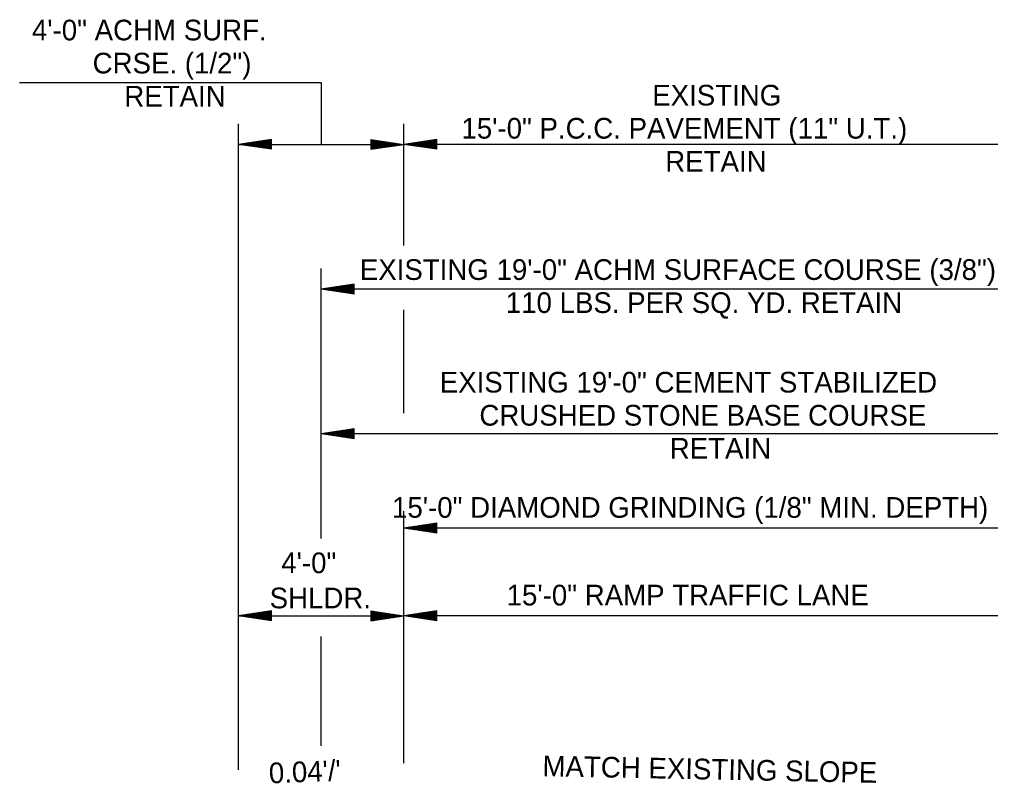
# Model space of a CAD drawing. Extents: x 60325 to 61047, y 53669 to 53767.
# Drawn here: x 60750.78 to 60774.27, y 53740.22 to 53758.7 of the extents above; entities that cross this region are included whole.
import ezdxf

# ---------------------------------------------------------------- set-up
doc = ezdxf.new("R2010")
doc.units = 0
doc.layers.add('R_Border', color=7, linetype='Continuous')
doc.layers.add('R_Border Prem', color=7, linetype='Continuous')

msp = doc.modelspace()

# ---------------------------------------------------------------- linework, layer by layer
at = {"layer": 'R_Border'}
for p, q in [((60760.077, 53740.712), (60760.077, 53746.806)), ((60760.877, 53746.514), (60760.077, 53746.394)), ((60760.877, 53746.494), (60760.21, 53746.394)), ((60760.877, 53746.474), (60760.348, 53746.394)), ((60760.877, 53746.454), (60760.481, 53746.394)), ((60760.877, 53746.434), (60760.617, 53746.394)), ((60760.877, 53746.274), (60760.877, 53746.514)), ((60775.077, 53746.394), (60760.077, 53746.394)), ((60760.877, 53746.274), (60760.077, 53746.394)), ((60760.877, 53746.294), (60760.21, 53746.394)), ((60760.877, 53746.315), (60760.348, 53746.394)), ((60760.877, 53746.335), (60760.481, 53746.394)), ((60760.877, 53746.356), (60760.617, 53746.394)), ((60760.877, 53746.413), (60760.75, 53746.394)), ((60760.877, 53746.376), (60760.75, 53746.394)), ((60760.877, 53744.393), (60760.077, 53744.273)), ((60760.877, 53744.373), (60760.21, 53744.273)), ((60760.877, 53744.352), (60760.348, 53744.273)), ((60760.877, 53744.332), (60760.481, 53744.273)), ((60760.877, 53744.312), (60760.617, 53744.273)), ((60760.877, 53744.153), (60760.877, 53744.393)), ((60775.077, 53744.273), (60760.077, 53744.273)), ((60760.877, 53744.153), (60760.077, 53744.273)), ((60760.877, 53744.173), (60760.21, 53744.273)), ((60760.877, 53744.193), (60760.348, 53744.273)), ((60760.877, 53744.213), (60760.481, 53744.273)), ((60760.877, 53744.234), (60760.617, 53744.273)), ((60760.877, 53744.292), (60760.75, 53744.273)), ((60760.877, 53744.254), (60760.75, 53744.273))]:
    msp.add_line(p, q, dxfattribs=at)
at = {"layer": 'R_Border Prem'}
for p, q in [((60750.78, 53757.18), (60758.077, 53757.18)), ((60758.077, 53757.18), (60758.077, 53755.68)), ((60756.077, 53745.055), (60756.077, 53756.18)), ((60760.077, 53753.232), (60760.077, 53756.18)), ((60756.877, 53755.8), (60756.077, 53755.68)), ((60756.077, 53755.68), (60760.077, 53755.68)), ((60756.877, 53755.56), (60756.077, 53755.68)), ((60756.877, 53755.78), (60756.21, 53755.68)), ((60756.877, 53755.58), (60756.21, 53755.68)), ((60756.877, 53755.76), (60756.348, 53755.68)), ((60756.877, 53755.6), (60756.348, 53755.68)), ((60756.877, 53755.74), (60756.481, 53755.68)), ((60756.877, 53755.62), (60756.481, 53755.68)), ((60756.877, 53755.719), (60756.617, 53755.68)), ((60756.877, 53755.641), (60756.617, 53755.68)), ((60756.877, 53755.699), (60756.75, 53755.68)), ((60756.877, 53755.661), (60756.75, 53755.68)), ((60756.877, 53755.56), (60756.877, 53755.8)), ((60759.277, 53755.8), (60760.077, 53755.68)), ((60759.277, 53755.8), (60759.277, 53755.56)), ((60759.277, 53755.78), (60759.943, 53755.68)), ((60759.277, 53755.76), (60759.806, 53755.68)), ((60759.277, 53755.74), (60759.672, 53755.68)), ((60759.277, 53755.719), (60759.537, 53755.68)), ((60759.277, 53755.699), (60759.403, 53755.68)), ((60759.277, 53755.56), (60760.077, 53755.68)), ((60759.277, 53755.641), (60759.537, 53755.68)), ((60759.277, 53755.6), (60759.806, 53755.68)), ((60759.277, 53755.58), (60759.943, 53755.68)), ((60759.277, 53755.62), (60759.672, 53755.68)), ((60759.277, 53755.661), (60759.403, 53755.68)), ((60760.877, 53755.8), (60760.077, 53755.68)), ((60775.077, 53755.68), (60760.077, 53755.68)), ((60760.877, 53755.56), (60760.077, 53755.68)), ((60760.877, 53755.78), (60760.21, 53755.68)), ((60760.877, 53755.58), (60760.21, 53755.68)), ((60760.877, 53755.76), (60760.348, 53755.68)), ((60760.877, 53755.6), (60760.348, 53755.68)), ((60760.877, 53755.74), (60760.481, 53755.68)), ((60760.877, 53755.62), (60760.481, 53755.68)), ((60760.877, 53755.719), (60760.617, 53755.68)), ((60760.877, 53755.641), (60760.617, 53755.68)), ((60760.877, 53755.699), (60760.75, 53755.68)), ((60760.877, 53755.661), (60760.75, 53755.68)), ((60760.877, 53755.56), (60760.877, 53755.8)), ((60758.077, 53746.884), (60758.077, 53752.68)), ((60758.877, 53752.3), (60758.077, 53752.18)), ((60758.877, 53752.06), (60758.877, 53752.3)), ((60777.077, 53752.18), (60758.077, 53752.18)), ((60758.877, 53752.06), (60758.077, 53752.18)), ((60758.877, 53752.28), (60758.21, 53752.18)), ((60758.877, 53752.08), (60758.21, 53752.18)), ((60758.877, 53752.26), (60758.348, 53752.18)), ((60758.877, 53752.1), (60758.348, 53752.18)), ((60758.877, 53752.24), (60758.481, 53752.18)), ((60758.877, 53752.12), (60758.481, 53752.18)), ((60758.877, 53752.219), (60758.617, 53752.18)), ((60758.877, 53752.141), (60758.617, 53752.18)), ((60758.877, 53752.199), (60758.75, 53752.18)), ((60758.877, 53752.161), (60758.75, 53752.18)), ((60760.077, 53749.18), (60760.077, 53751.68)), ((60758.877, 53748.8), (60758.077, 53748.68)), ((60758.877, 53748.78), (60758.21, 53748.68)), ((60758.877, 53748.56), (60758.877, 53748.8)), ((60777.077, 53748.68), (60758.077, 53748.68)), ((60758.877, 53748.56), (60758.077, 53748.68)), ((60758.877, 53748.58), (60758.21, 53748.68)), ((60758.877, 53748.76), (60758.348, 53748.68)), ((60758.877, 53748.6), (60758.348, 53748.68)), ((60758.877, 53748.74), (60758.481, 53748.68)), ((60758.877, 53748.62), (60758.481, 53748.68)), ((60758.877, 53748.719), (60758.617, 53748.68)), ((60758.877, 53748.641), (60758.617, 53748.68)), ((60758.877, 53748.699), (60758.75, 53748.68)), ((60758.877, 53748.661), (60758.75, 53748.68)), ((60758.077, 53746.145), (60758.077, 53746.884)), ((60756.077, 53740.552), (60756.077, 53745.055)), ((60756.877, 53744.393), (60756.077, 53744.273)), ((60756.877, 53744.373), (60756.21, 53744.273)), ((60756.877, 53744.352), (60756.348, 53744.273)), ((60756.877, 53744.332), (60756.481, 53744.273)), ((60756.877, 53744.312), (60756.617, 53744.273)), ((60756.877, 53744.153), (60756.877, 53744.393)), ((60759.277, 53744.393), (60760.077, 53744.273)), ((60759.277, 53744.393), (60759.277, 53744.153)), ((60759.277, 53744.373), (60759.943, 53744.273)), ((60759.277, 53744.352), (60759.806, 53744.273)), ((60759.277, 53744.332), (60759.672, 53744.273)), ((60759.277, 53744.312), (60759.537, 53744.273)), ((60756.077, 53744.273), (60760.077, 53744.273)), ((60756.877, 53744.153), (60756.077, 53744.273)), ((60756.877, 53744.173), (60756.21, 53744.273)), ((60756.877, 53744.193), (60756.348, 53744.273)), ((60756.877, 53744.213), (60756.481, 53744.273)), ((60756.877, 53744.234), (60756.617, 53744.273)), ((60756.877, 53744.292), (60756.75, 53744.273)), ((60756.877, 53744.254), (60756.75, 53744.273)), ((60759.277, 53744.292), (60759.403, 53744.273)), ((60759.277, 53744.153), (60760.077, 53744.273)), ((60759.277, 53744.234), (60759.537, 53744.273)), ((60759.277, 53744.193), (60759.806, 53744.273)), ((60759.277, 53744.173), (60759.943, 53744.273)), ((60759.277, 53744.213), (60759.672, 53744.273)), ((60759.277, 53744.254), (60759.403, 53744.273)), ((60758.077, 53741.132), (60758.077, 53743.773))]:
    msp.add_line(p, q, dxfattribs=at)

# ---------------------------------------------------------------- texts
at = {"layer": 'R_Border'}
for s, p in [('15\'-0" DIAMOND GRINDING (1/8" MIN. DEPTH)', (60759.793, 53746.648)), ('15\'-0" RAMP TRAFFIC LANE', (60762.565, 53744.527))]:
    msp.add_text(s, height=0.5, dxfattribs=at).set_placement(p)
msp.add_text('MATCH EXISTING SLOPE', height=0.5, rotation=358.8542, dxfattribs=at).set_placement((60763.428, 53740.397))
at = {"layer": 'R_Border Prem'}
for s, p in [('4\'-0" ACHM SURF.', (60751.082, 53758.195)), ('CRSE. (1/2")', (60752.551, 53757.395)), ('RETAIN', (60753.317, 53756.595)), ('EXISTING', (60766.087, 53756.619)), ('15\'-0" P.C.C. PAVEMENT (11" U.T.)', (60761.472, 53755.819)), ('RETAIN', (60766.402, 53755.019)), (' EXISTING 19\'-0" ACHM SURFACE COURSE (3/8")', (60758.828, 53752.401)), ('110 LBS. PER SQ. YD. RETAIN', (60762.545, 53751.601)), ('EXISTING 19\'-0" CEMENT STABILIZED', (60760.947, 53749.677)), ('CRUSHED STONE BASE COURSE', (60761.906, 53748.877)), ('RETAIN', (60766.511, 53748.077)), ('4\'-0"', (60757.113, 53745.308)), ('SHLDR.', (60756.832, 53744.458))]:
    msp.add_text(s, height=0.5, dxfattribs=at).set_placement(p)
msp.add_text("0.04'/'", height=0.5, rotation=2.2906, dxfattribs=at).set_placement((60756.824, 53740.221))

doc.saveas('drawing.dxf')
